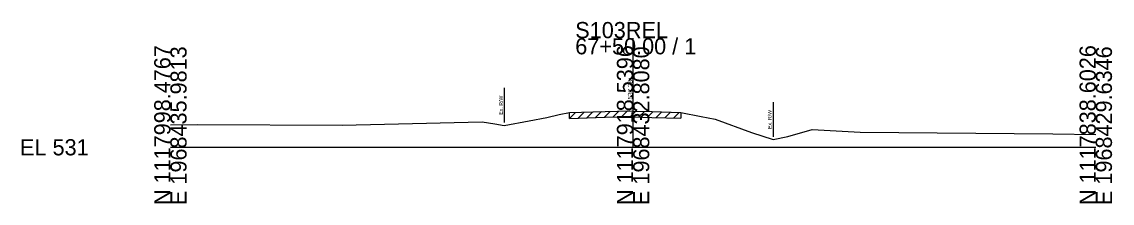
# Model space of a CAD drawing. Extents: x -26 to 163, y -10 to 24518.
# Drawn here: x -25.7 to 162.8, y 15990.3 to 16021.7 of the extents above; entities that cross this region are included whole.
import ezdxf

# ---------------------------------------------------------------- set-up
doc = ezdxf.new("R2010")
doc.units = 0
for name, color, linetype in [('RD_GPK_XS_Cell', 7, 'Continuous'), ('RD_XS_ExGround', 7, 'Continuous'), ('RD_XS_ExPaveRet', 7, 'Continuous'), ('RD_XS_ExRW', 7, 'Continuous'), ('RD_XS_TX_Elev_EX', 7, 'Continuous')]:
    doc.layers.add(name, color=color, linetype=linetype)

msp = doc.modelspace()

# ---------------------------------------------------------------- linework, layer by layer
at = {"layer": 'RD_GPK_XS_Cell'}
for p, q in [((80, 16000), (80, 16018.9)), ((0, 16000), (80, 16000)), ((80, 16000), (160, 16000))]:
    msp.add_line(p, q, dxfattribs=at)
at = {"layer": 'RD_XS_ExGround'}
msp.add_lwpolyline([(0, 16003.91), (4.73, 16003.97), (29.7, 16003.81), (37.01, 16003.98), (53.91, 16004.39), (56.1, 16004.09), (57.73, 16003.8), (62.05, 16004.58), (65.07, 16005.14), (67.24, 16005.65), (69.01, 16006.01), (75.15, 16006.19), (79.45, 16006.3), (80, 16006.28), (83.26, 16006.18), (88.24, 16006.02), (91.79, 16005.33), (94.17, 16004.89), (100.49, 16002.56), (104.2, 16001.32), (106.76, 16001.87), (110.97, 16003.08), (119.27, 16002.63), (152.57, 16002.35), (160, 16002.22)], dxfattribs=at)
at = {"layer": 'RD_XS_ExPaveRet'}
for p, q in [((69.01, 16005.01), (70.04, 16006.04)), ((69.01, 16005.01), (69.01, 16006.01)), ((69.01, 16005.01), (75.15, 16005.19)), ((70.51, 16005.06), (71.54, 16006.09)), ((72.01, 16005.1), (73.04, 16006.13)), ((73.51, 16005.14), (74.54, 16006.17)), ((75.01, 16005.18), (76.04, 16006.21)), ((75.15, 16005.19), (79.45, 16005.3)), ((76.51, 16005.22), (77.54, 16006.25)), ((78.01, 16005.26), (79.04, 16006.29)), ((79.45, 16005.3), (80, 16005.28)), ((79.51, 16005.3), (80.48, 16006.27)), ((80, 16005.28), (83.26, 16005.18)), ((81.01, 16005.25), (81.98, 16006.22)), ((82.51, 16005.2), (83.48, 16006.17)), ((83.26, 16005.18), (88.24, 16005.02)), ((84.01, 16005.15), (84.98, 16006.12)), ((85.51, 16005.1), (86.48, 16006.07)), ((87.01, 16005.06), (87.98, 16006.02)), ((88.24, 16006.02), (88.24, 16005.02))]:
    msp.add_line(p, q, dxfattribs=at)
at = {"layer": 'RD_XS_ExRW'}
for p, q in [((57.73, 16010.3), (57.73, 16004.3)), ((104.2, 16007.82), (104.2, 16001.82))]:
    msp.add_line(p, q, dxfattribs=at)

# ---------------------------------------------------------------- texts
at = {"layer": 'RD_GPK_XS_Cell'}
for s, p in [('S103REL', (70, 16018.9)), ('67+50.00 / 1', (70, 16016.1)), ('EL 531', (-26, 15998.6))]:
    msp.add_text(s, height=2.8, dxfattribs=at).set_placement(p)
for s, p in [('N 1117998.4767', (0, 15990)), ('E 1968435.9813', (2.8, 15990)), ('N 1117918.5396', (80, 15990)), ('E 1968432.8080', (82.8, 15990)), ('N 1117838.6026', (160, 15990)), ('E 1968429.6346', (162.8, 15990))]:
    msp.add_text(s, height=2.8, rotation=90, dxfattribs=at).set_placement(p)
at = {"layer": 'RD_XS_ExRW'}
for p in [(57.48, 16005.65), (103.95, 16003.17)]:
    msp.add_text('Ex. R/W ', height=0.65, rotation=90, dxfattribs=at).set_placement(p)
at = {"layer": 'RD_XS_TX_Elev_EX'}
msp.add_text('537.28', height=0.8, rotation=90, dxfattribs=at).set_placement((79.9, 16008.28))

doc.saveas('drawing.dxf')
